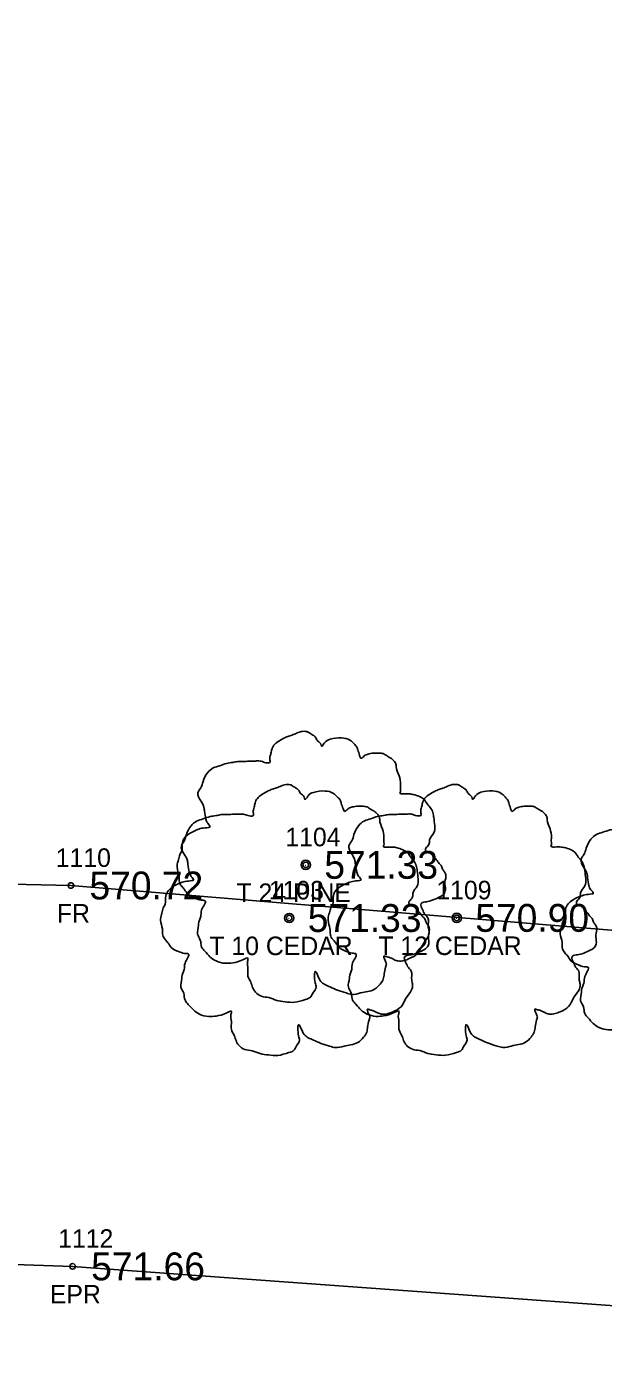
# Model space of a CAD drawing. Extents: x 1529475 to 1532053, y 876698 to 877911.
# Drawn here: x 1531183.3 to 1531214.4, y 877286.3 to 877357.7 of the extents above; entities that cross this region are included whole.
import ezdxf

# ---------------------------------------------------------------- set-up
doc = ezdxf.new("R2010")
doc.units = 0
for name, color, linetype in [('RD_EX_Fence_Other', 7, 'Continuous'), ('RD_EX_Fence_Other_txCode', 7, 'Continuous'), ('RD_EX_Road', 7, 'Continuous'), ('RD_EX_Road_txCode', 7, 'Continuous'), ('RD_EX_TX_Fence_Other_ELEV', 7, 'Continuous'), ('RD_EX_TX_Road_ELEV', 7, 'Continuous'), ('RD_EX_TX_VEG_ELEV', 7, 'Continuous'), ('RD_EX_VEG', 7, 'Continuous'), ('RD_EX_VEG_txCode', 7, 'Continuous'), ('RD_SMD_Locator', 7, 'Continuous')]:
    doc.layers.add(name, color=color, linetype=linetype)

msp = doc.modelspace()

# ---------------------------------------------------------------- linework, layer by layer
at = {"layer": 'RD_EX_Fence_Other'}
msp.add_lwpolyline([(1531287.683, 877345.243), (1531281.932, 877317.977), (1531278.086, 877303.259), (1531232.889, 877307.565), (1531185.71, 877311.458), (1531137.538, 877312.532), (1531141.511, 877357.73)], dxfattribs=at)
at = {"layer": 'RD_EX_Road'}
msp.add_lwpolyline([(1531606.641, 877133.837), (1531579.15, 877155.048), (1531564.866, 877165.268), (1531535.216, 877186.029), (1531511.532, 877200.27), (1531474.57, 877218.901), (1531430.451, 877239.347), (1531404.48, 877249.379), (1531382.323, 877256.431), (1531333.233, 877270.709), (1531303.666, 877277.444), (1531276.518, 877282.709), (1531237.324, 877287.202), (1531185.802, 877290.94), (1531132.609, 877292.767), (1531081.114, 877292.384), (1531038.69, 877288.667), (1530976.423, 877285.451), (1530941.057, 877284.256)], dxfattribs=at)
at = {"layer": 'RD_EX_VEG'}
for centre, radius in [((1531198.375, 877312.569), 0.25), ((1531198.363, 877312.55), 0.0001), ((1531197.482, 877309.705), 0.25), ((1531197.469, 877309.686), 0.0001), ((1531206.516, 877309.712), 0.25), ((1531206.503, 877309.693), 0.0001)]:
    msp.add_circle(centre, radius, dxfattribs=at)
for points in [[(1531198.507, 877319.736), (1531198.207, 877319.761), (1531197.883, 877319.661), (1531197.633, 877319.561), (1531197.408, 877319.486), (1531197.183, 877319.386), (1531196.883, 877319.211), (1531196.658, 877319.011), (1531196.533, 877318.761), (1531196.483, 877318.536), (1531196.433, 877318.262), (1531196.433, 877318.087), (1531196.308, 877318.062), (1531196.158, 877318.087), (1531195.908, 877318.162), (1531195.658, 877318.162), (1531195.409, 877318.162), (1531195.059, 877318.137), (1531194.709, 877318.137), (1531194.434, 877318.087), (1531194.109, 877318.037), (1531193.734, 877317.912), (1531193.384, 877317.787), (1531193.085, 877317.537), (1531192.835, 877317.062), (1531192.71, 877316.712), (1531192.56, 877316.462), (1531192.71, 877316.013), (1531192.885, 877315.663), (1531192.91, 877315.463), (1531192.985, 877315.038), (1531193.085, 877314.813), (1531193.21, 877314.613), (1531193.135, 877314.588), (1531192.76, 877314.538), (1531192.46, 877314.438), (1531192.035, 877314.213), (1531191.81, 877313.988), (1531191.71, 877313.663), (1531191.685, 877313.314), (1531191.585, 877313.114), (1531191.51, 877312.839), (1531191.485, 877312.764), (1531191.435, 877312.439), (1531191.535, 877311.989), (1531191.56, 877311.639), (1531191.685, 877311.414), (1531191.835, 877311.24), (1531192.01, 877310.99), (1531192.41, 877310.765), (1531192.735, 877310.665), (1531192.935, 877310.64), (1531192.76, 877310.14), (1531192.71, 877309.79), (1531192.585, 877309.39), (1531192.585, 877309.315), (1531192.535, 877308.841), (1531192.685, 877308.516), (1531192.76, 877308.141), (1531192.935, 877307.916), (1531193.21, 877307.616), (1531193.534, 877307.391), (1531194.034, 877307.266), (1531194.434, 877307.291), (1531195.009, 877307.466), (1531195.259, 877307.541), (1531195.234, 877307.366), (1531195.259, 877306.991), (1531195.259, 877306.567), (1531195.409, 877306.242), (1531195.509, 877305.967), (1531195.658, 877305.717), (1531195.983, 877305.492), (1531196.383, 877305.417), (1531196.808, 877305.267), (1531197.258, 877305.192), (1531197.758, 877305.167), (1531198.357, 877305.317), (1531198.632, 877305.442), (1531198.732, 877305.617), (1531198.932, 877305.992), (1531198.882, 877306.217), (1531198.907, 877306.817), (1531199.007, 877306.642), (1531199.182, 877306.292), (1531199.682, 877305.992), (1531200.082, 877305.817), (1531200.556, 877305.667), (1531200.856, 877305.592), (1531201.331, 877305.667), (1531201.706, 877305.742), (1531202.081, 877305.867), (1531202.381, 877306.142), (1531202.555, 877306.417), (1531202.605, 877306.692), (1531202.68, 877307.066), (1531202.73, 877307.241)], [(1531202.73, 877307.241), (1531202.655, 877307.416), (1531202.605, 877307.666), (1531202.68, 877307.641), (1531202.855, 877307.591), (1531203.13, 877307.466), (1531203.355, 877307.391), (1531203.68, 877307.416), (1531203.955, 877307.516), (1531204.405, 877307.791), (1531204.68, 877308.266), (1531204.954, 877308.666), (1531205.029, 877308.991), (1531204.979, 877309.215), (1531204.954, 877309.715), (1531204.754, 877309.965), (1531204.704, 877310.09), (1531204.605, 877310.49), (1531204.68, 877310.54), (1531204.954, 877310.59), (1531205.329, 877310.715), (1531205.604, 877310.84), (1531205.829, 877311.015), (1531205.904, 877311.24), (1531205.879, 877311.639), (1531205.929, 877312.039), (1531205.854, 877312.189), (1531205.754, 877312.339), (1531205.679, 877312.539), (1531205.529, 877312.689), (1531205.429, 877312.839), (1531205.329, 877312.939), (1531205.204, 877313.089), (1531205.029, 877313.214), (1531204.879, 877313.264), (1531204.829, 877313.414), (1531204.979, 877313.614), (1531205.029, 877313.713), (1531205.054, 877313.938), (1531205.279, 877314.288), (1531205.329, 877314.688), (1531205.279, 877315.113), (1531205.229, 877315.388), (1531205.079, 877315.663), (1531204.879, 877315.913), (1531204.754, 877316.087), (1531204.58, 877316.212), (1531204.255, 877316.337), (1531204.005, 877316.387), (1531203.655, 877316.387), (1531203.455, 877316.437), (1531203.48, 877316.487), (1531203.48, 877316.637), (1531203.48, 877316.912), (1531203.405, 877317.362), (1531203.255, 877317.862), (1531203.255, 877317.887), (1531203.155, 877318.137), (1531202.93, 877318.336), (1531202.755, 877318.436), (1531202.555, 877318.561), (1531202.306, 877318.586), (1531202.006, 877318.586), (1531201.731, 877318.536), (1531201.531, 877318.436), (1531201.356, 877318.311), (1531201.281, 877318.461), (1531201.181, 877318.761), (1531201.131, 877318.911), (1531200.981, 877319.086), (1531200.756, 877319.286), (1531200.306, 877319.411), (1531199.682, 877319.336), (1531199.382, 877319.136), (1531199.232, 877318.961), (1531199.182, 877319.086), (1531198.982, 877319.286), (1531198.882, 877319.461), (1531198.707, 877319.586), (1531198.557, 877319.686), (1531198.457, 877319.736)], [(1531197.614, 877316.872), (1531197.314, 877316.897), (1531196.989, 877316.797), (1531196.739, 877316.697), (1531196.514, 877316.622), (1531196.289, 877316.522), (1531195.99, 877316.347), (1531195.765, 877316.147), (1531195.64, 877315.897), (1531195.59, 877315.672), (1531195.54, 877315.398), (1531195.54, 877315.223), (1531195.415, 877315.198), (1531195.265, 877315.223), (1531195.015, 877315.298), (1531194.765, 877315.298), (1531194.515, 877315.298), (1531194.165, 877315.273), (1531193.815, 877315.273), (1531193.541, 877315.223), (1531193.216, 877315.173), (1531192.841, 877315.048), (1531192.491, 877314.923), (1531192.191, 877314.673), (1531191.941, 877314.198), (1531191.816, 877313.848), (1531191.666, 877313.598), (1531191.816, 877313.149), (1531191.991, 877312.799), (1531192.016, 877312.599), (1531192.091, 877312.174), (1531192.191, 877311.949), (1531192.316, 877311.749), (1531192.241, 877311.724), (1531191.866, 877311.674), (1531191.566, 877311.574), (1531191.142, 877311.349), (1531190.917, 877311.124), (1531190.817, 877310.8), (1531190.792, 877310.45), (1531190.692, 877310.25), (1531190.617, 877309.975), (1531190.592, 877309.9), (1531190.542, 877309.575), (1531190.642, 877309.125), (1531190.667, 877308.775), (1531190.792, 877308.551), (1531190.942, 877308.376), (1531191.117, 877308.126), (1531191.516, 877307.901), (1531191.841, 877307.801), (1531192.041, 877307.776), (1531191.866, 877307.276), (1531191.816, 877306.926), (1531191.691, 877306.526), (1531191.691, 877306.452), (1531191.641, 877305.977), (1531191.791, 877305.652), (1531191.866, 877305.277), (1531192.041, 877305.052), (1531192.316, 877304.752), (1531192.641, 877304.527), (1531193.141, 877304.402), (1531193.541, 877304.427), (1531194.115, 877304.602), (1531194.365, 877304.677), (1531194.34, 877304.502), (1531194.365, 877304.127), (1531194.365, 877303.703), (1531194.515, 877303.378), (1531194.615, 877303.103), (1531194.765, 877302.853), (1531195.09, 877302.628), (1531195.49, 877302.553), (1531195.915, 877302.403), (1531196.364, 877302.328), (1531196.864, 877302.303), (1531197.464, 877302.453), (1531197.739, 877302.578), (1531197.839, 877302.753), (1531198.039, 877303.128), (1531197.989, 877303.353), (1531198.014, 877303.953), (1531198.114, 877303.778), (1531198.289, 877303.428), (1531198.788, 877303.128), (1531199.188, 877302.953), (1531199.663, 877302.803), (1531199.963, 877302.728), (1531200.438, 877302.803), (1531200.812, 877302.878), (1531201.187, 877303.003), (1531201.487, 877303.278), (1531201.662, 877303.553), (1531201.712, 877303.828), (1531201.787, 877304.202), (1531201.837, 877304.377)], [(1531201.837, 877304.377), (1531201.762, 877304.552), (1531201.712, 877304.802), (1531201.787, 877304.777), (1531201.962, 877304.727), (1531202.237, 877304.602), (1531202.462, 877304.527), (1531202.787, 877304.552), (1531203.061, 877304.652), (1531203.511, 877304.927), (1531203.786, 877305.402), (1531204.061, 877305.802), (1531204.136, 877306.127), (1531204.086, 877306.352), (1531204.061, 877306.851), (1531203.861, 877307.101), (1531203.811, 877307.226), (1531203.711, 877307.626), (1531203.786, 877307.676), (1531204.061, 877307.726), (1531204.436, 877307.851), (1531204.711, 877307.976), (1531204.936, 877308.151), (1531205.011, 877308.376), (1531204.986, 877308.775), (1531205.036, 877309.175), (1531204.961, 877309.325), (1531204.861, 877309.475), (1531204.786, 877309.675), (1531204.636, 877309.825), (1531204.536, 877309.975), (1531204.436, 877310.075), (1531204.311, 877310.225), (1531204.136, 877310.35), (1531203.986, 877310.4), (1531203.936, 877310.55), (1531204.086, 877310.75), (1531204.136, 877310.85), (1531204.161, 877311.074), (1531204.386, 877311.424), (1531204.436, 877311.824), (1531204.386, 877312.249), (1531204.336, 877312.524), (1531204.186, 877312.799), (1531203.986, 877313.049), (1531203.861, 877313.224), (1531203.686, 877313.348), (1531203.361, 877313.473), (1531203.111, 877313.523), (1531202.762, 877313.523), (1531202.562, 877313.573), (1531202.587, 877313.623), (1531202.587, 877313.773), (1531202.587, 877314.048), (1531202.512, 877314.498), (1531202.362, 877314.998), (1531202.362, 877315.023), (1531202.262, 877315.273), (1531202.037, 877315.473), (1531201.862, 877315.572), (1531201.662, 877315.697), (1531201.412, 877315.722), (1531201.112, 877315.722), (1531200.837, 877315.672), (1531200.637, 877315.572), (1531200.463, 877315.448), (1531200.388, 877315.597), (1531200.288, 877315.897), (1531200.238, 877316.047), (1531200.088, 877316.222), (1531199.863, 877316.422), (1531199.413, 877316.547), (1531198.788, 877316.472), (1531198.488, 877316.272), (1531198.338, 877316.097), (1531198.289, 877316.222), (1531198.089, 877316.422), (1531197.989, 877316.597), (1531197.814, 877316.722), (1531197.664, 877316.822), (1531197.564, 877316.872)], [(1531206.648, 877316.879), (1531206.348, 877316.904), (1531206.023, 877316.804), (1531205.773, 877316.704), (1531205.548, 877316.629), (1531205.323, 877316.529), (1531205.024, 877316.354), (1531204.799, 877316.154), (1531204.674, 877315.904), (1531204.624, 877315.679), (1531204.574, 877315.405), (1531204.574, 877315.23), (1531204.449, 877315.205), (1531204.299, 877315.23), (1531204.049, 877315.305), (1531203.799, 877315.305), (1531203.549, 877315.305), (1531203.199, 877315.28), (1531202.849, 877315.28), (1531202.575, 877315.23), (1531202.25, 877315.18), (1531201.875, 877315.055), (1531201.525, 877314.93), (1531201.225, 877314.68), (1531200.975, 877314.205), (1531200.85, 877313.855), (1531200.7, 877313.605), (1531200.85, 877313.156), (1531201.025, 877312.806), (1531201.05, 877312.606), (1531201.125, 877312.181), (1531201.225, 877311.956), (1531201.35, 877311.756), (1531201.275, 877311.731), (1531200.9, 877311.681), (1531200.6, 877311.581), (1531200.176, 877311.356), (1531199.951, 877311.131), (1531199.851, 877310.806), (1531199.826, 877310.457), (1531199.726, 877310.257), (1531199.651, 877309.982), (1531199.626, 877309.907), (1531199.576, 877309.582), (1531199.676, 877309.132), (1531199.701, 877308.782), (1531199.826, 877308.557), (1531199.976, 877308.383), (1531200.151, 877308.133), (1531200.55, 877307.908), (1531200.875, 877307.808), (1531201.075, 877307.783), (1531200.9, 877307.283), (1531200.85, 877306.933), (1531200.725, 877306.533), (1531200.725, 877306.458), (1531200.675, 877305.984), (1531200.825, 877305.659), (1531200.9, 877305.284), (1531201.075, 877305.059), (1531201.35, 877304.759), (1531201.675, 877304.534), (1531202.175, 877304.409), (1531202.575, 877304.434), (1531203.149, 877304.609), (1531203.399, 877304.684), (1531203.374, 877304.509), (1531203.399, 877304.134), (1531203.399, 877303.71), (1531203.549, 877303.385), (1531203.649, 877303.11), (1531203.799, 877302.86), (1531204.124, 877302.635), (1531204.524, 877302.56), (1531204.949, 877302.41), (1531205.398, 877302.335), (1531205.898, 877302.31), (1531206.498, 877302.46), (1531206.773, 877302.585), (1531206.873, 877302.76), (1531207.073, 877303.135), (1531207.023, 877303.36), (1531207.048, 877303.96), (1531207.148, 877303.785), (1531207.323, 877303.435), (1531207.822, 877303.135), (1531208.222, 877302.96), (1531208.697, 877302.81), (1531208.997, 877302.735), (1531209.472, 877302.81), (1531209.846, 877302.885), (1531210.221, 877303.01), (1531210.521, 877303.285), (1531210.696, 877303.56), (1531210.746, 877303.835), (1531210.821, 877304.209), (1531210.871, 877304.384)], [(1531210.871, 877304.384), (1531210.796, 877304.559), (1531210.746, 877304.809), (1531210.821, 877304.784), (1531210.996, 877304.734), (1531211.271, 877304.609), (1531211.496, 877304.534), (1531211.821, 877304.559), (1531212.095, 877304.659), (1531212.545, 877304.934), (1531212.82, 877305.409), (1531213.095, 877305.809), (1531213.17, 877306.134), (1531213.12, 877306.358), (1531213.095, 877306.858), (1531212.895, 877307.108), (1531212.845, 877307.233), (1531212.745, 877307.633), (1531212.82, 877307.683), (1531213.095, 877307.733), (1531213.47, 877307.858), (1531213.745, 877307.983), (1531213.97, 877308.158), (1531214.045, 877308.383), (1531214.02, 877308.782), (1531214.07, 877309.182), (1531213.995, 877309.332), (1531213.895, 877309.482), (1531213.82, 877309.682), (1531213.67, 877309.832), (1531213.57, 877309.982), (1531213.47, 877310.082), (1531213.345, 877310.232), (1531213.17, 877310.357), (1531213.02, 877310.407), (1531212.97, 877310.557), (1531213.12, 877310.757), (1531213.17, 877310.856), (1531213.195, 877311.081), (1531213.42, 877311.431), (1531213.47, 877311.831), (1531213.42, 877312.256), (1531213.37, 877312.531), (1531213.22, 877312.806), (1531213.02, 877313.056), (1531212.895, 877313.23), (1531212.72, 877313.355), (1531212.395, 877313.48), (1531212.145, 877313.53), (1531211.796, 877313.53), (1531211.596, 877313.58), (1531211.621, 877313.63), (1531211.621, 877313.78), (1531211.621, 877314.055), (1531211.546, 877314.505), (1531211.396, 877315.005), (1531211.396, 877315.03), (1531211.296, 877315.28), (1531211.071, 877315.479), (1531210.896, 877315.579), (1531210.696, 877315.704), (1531210.446, 877315.729), (1531210.146, 877315.729), (1531209.871, 877315.679), (1531209.671, 877315.579), (1531209.497, 877315.454), (1531209.422, 877315.604), (1531209.322, 877315.904), (1531209.272, 877316.054), (1531209.122, 877316.229), (1531208.897, 877316.429), (1531208.447, 877316.554), (1531207.822, 877316.479), (1531207.522, 877316.279), (1531207.372, 877316.104), (1531207.323, 877316.229), (1531207.123, 877316.429), (1531207.023, 877316.604), (1531206.848, 877316.729), (1531206.698, 877316.829), (1531206.598, 877316.879)], [(1531219.17, 877316.149), (1531218.871, 877316.174), (1531218.546, 877316.074), (1531218.296, 877315.974), (1531218.071, 877315.899), (1531217.846, 877315.799), (1531217.546, 877315.624), (1531217.321, 877315.424), (1531217.196, 877315.174), (1531217.146, 877314.949), (1531217.096, 877314.674), (1531217.096, 877314.499), (1531216.971, 877314.474), (1531216.821, 877314.499), (1531216.572, 877314.574), (1531216.322, 877314.574), (1531216.072, 877314.574), (1531215.722, 877314.549), (1531215.372, 877314.549), (1531215.097, 877314.499), (1531214.772, 877314.449), (1531214.398, 877314.324), (1531214.048, 877314.199), (1531213.748, 877313.949), (1531213.498, 877313.475), (1531213.373, 877313.125), (1531213.223, 877312.875), (1531213.373, 877312.425), (1531213.548, 877312.075), (1531213.573, 877311.875), (1531213.648, 877311.451), (1531213.748, 877311.226), (1531213.873, 877311.026), (1531213.798, 877311.001), (1531213.423, 877310.951), (1531213.123, 877310.851), (1531212.698, 877310.626), (1531212.473, 877310.401), (1531212.373, 877310.076), (1531212.348, 877309.726), (1531212.249, 877309.526), (1531212.174, 877309.252), (1531212.149, 877309.177), (1531212.099, 877308.852), (1531212.199, 877308.402), (1531212.224, 877308.052), (1531212.348, 877307.827), (1531212.498, 877307.652), (1531212.673, 877307.402), (1531213.073, 877307.177), (1531213.398, 877307.077), (1531213.598, 877307.053), (1531213.423, 877306.553), (1531213.373, 877306.203), (1531213.248, 877305.803), (1531213.248, 877305.728), (1531213.198, 877305.253), (1531213.348, 877304.928), (1531213.423, 877304.554), (1531213.598, 877304.329), (1531213.873, 877304.029), (1531214.198, 877303.804), (1531214.697, 877303.679), (1531215.097, 877303.704), (1531215.672, 877303.879), (1531215.922, 877303.954), (1531215.897, 877303.779), (1531215.922, 877303.404), (1531215.922, 877302.979), (1531216.072, 877302.654), (1531216.172, 877302.38), (1531216.322, 877302.13), (1531216.647, 877301.905), (1531217.046, 877301.83), (1531217.471, 877301.68), (1531217.921, 877301.605), (1531218.421, 877301.58), (1531219.021, 877301.73), (1531219.295, 877301.855), (1531219.395, 877302.03), (1531219.595, 877302.405), (1531219.545, 877302.629), (1531219.57, 877303.229), (1531219.67, 877303.054), (1531219.845, 877302.704), (1531220.345, 877302.405), (1531220.745, 877302.23), (1531221.22, 877302.08), (1531221.519, 877302.005), (1531221.994, 877302.08), (1531222.369, 877302.155), (1531222.744, 877302.28), (1531223.044, 877302.554), (1531223.219, 877302.829), (1531223.269, 877303.104), (1531223.344, 877303.479), (1531223.394, 877303.654)]]:
    msp.add_spline(points, degree=3, dxfattribs=at)
at = {"layer": 'RD_SMD_Locator'}
for centre in [(1531198.375, 877312.569), (1531185.71, 877311.458), (1531197.482, 877309.705), (1531206.516, 877309.712), (1531185.802, 877290.94)]:
    msp.add_circle(centre, 0.15, dxfattribs=at)

# ---------------------------------------------------------------- texts
at = {"layer": 'RD_EX_Fence_Other_txCode'}
for s, p in [('1110', (1531184.891, 877312.458)), ('FR', (1531184.954, 877309.458))]:
    msp.add_text(s, height=1, dxfattribs=at).set_placement(p)
at = {"layer": 'RD_EX_Road_txCode'}
for s, p in [('1112', (1531185.022, 877291.94)), ('EPR', (1531184.574, 877288.94))]:
    msp.add_text(s, height=1, dxfattribs=at).set_placement(p)
at = {"layer": 'RD_EX_TX_Fence_Other_ELEV'}
msp.add_text('570.72', height=1.5, dxfattribs=at).set_placement((1531186.71, 877310.708))
at = {"layer": 'RD_EX_TX_Road_ELEV'}
msp.add_text('571.66', height=1.5, dxfattribs=at).set_placement((1531186.802, 877290.19))
at = {"layer": 'RD_EX_TX_VEG_ELEV'}
for s, p in [('571.33', (1531199.375, 877311.819)), ('571.33', (1531198.482, 877308.955)), ('570.90', (1531207.516, 877308.962))]:
    msp.add_text(s, height=1.5, dxfattribs=at).set_placement(p)
at = {"layer": 'RD_EX_VEG_txCode'}
for s, p in [('1104', (1531197.273, 877313.569)), ('1109', (1531205.414, 877310.712)), ('T 24 PINE', (1531194.639, 877310.569)), ('1103', (1531196.38, 877310.705)), ('T 10 CEDAR', (1531193.175, 877307.705)), ('T 12 CEDAR', (1531202.288, 877307.712))]:
    msp.add_text(s, height=1, dxfattribs=at).set_placement(p)

doc.saveas('drawing.dxf')
